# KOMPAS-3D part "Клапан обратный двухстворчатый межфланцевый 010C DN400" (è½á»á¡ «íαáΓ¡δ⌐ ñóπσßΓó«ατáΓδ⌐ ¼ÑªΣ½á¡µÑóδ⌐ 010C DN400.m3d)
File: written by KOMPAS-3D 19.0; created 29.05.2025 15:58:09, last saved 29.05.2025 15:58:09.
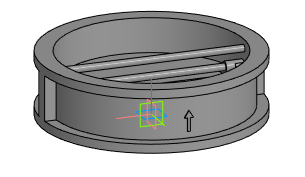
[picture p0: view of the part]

Document properties: Полное имя файла: E:\Dendor Работа Сачек\3D для проекитирвщиков\5.2 Тип 010C, 010C.Y Клапан обратный двухстворчатый межфланцевый\stp_Клапан обратный двухстворчатый межфланцевый 010C\Клапан обратный двухстворчатый межфланцевый 010C DN400.m3d

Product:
- Part/product: Клапан обратный двухстворчатый межфланцевый 010C DN400

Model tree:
1. Операция без истории:1  (labels: Клапан обратный двухстворчатый межфланцевый 010C DN400)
